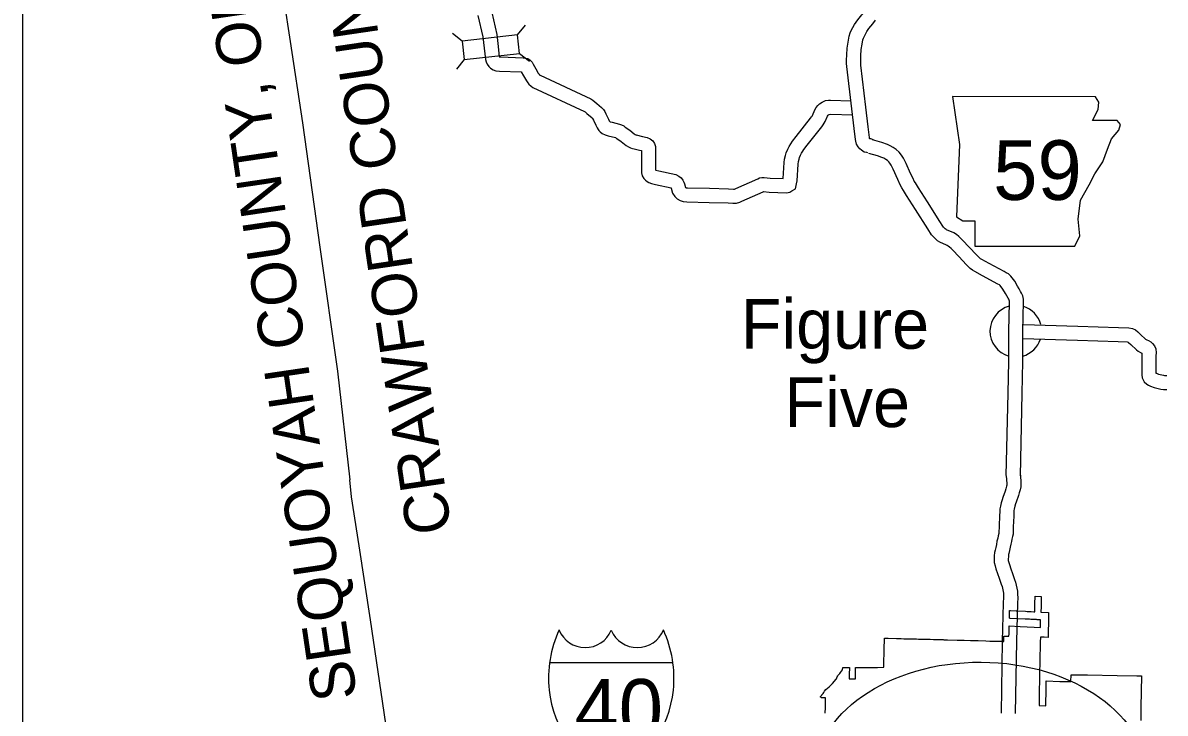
# Model space of a CAD drawing. Extents: x 535214 to 694517, y 381272 to 484355.
# Drawn here: x 535214 to 547357, y 463649 to 470990 of the extents above; entities that cross this region are included whole.
import ezdxf

# ---------------------------------------------------------------- set-up
doc = ezdxf.new("R2010")
doc.units = 0
for name, color, linetype in [('1', 7, 'Continuous'), ('21', 7, 'Continuous'), ('Level 1', 7, 'Continuous'), ('Level 10', 7, 'Continuous'), ('Level 11', 7, 'Continuous'), ('Level 20', 7, 'Continuous'), ('Level 21', 7, 'Continuous'), ('Level 23', 7, 'Continuous'), ('Level 24', 7, 'Continuous'), ('Level 6', 7, 'Continuous')]:
    doc.layers.add(name, color=color, linetype=linetype)

msp = doc.modelspace()

# ---------------------------------------------------------------- linework, layer by layer
at = {"layer": '1'}
msp.add_lwpolyline([(535214, 480223), (566227, 480223), (566227, 448175), (535214, 448175)], close=True, dxfattribs=at)
msp.add_ellipse((545395, 462932), major_axis=(1782, -9), ratio=0.706717, dxfattribs=at)
at = {"layer": 'Level 1'}
for points in [[(537589, 474021), (537668, 473434), (537852, 472112), (538054, 470793), (538187, 469927), (538371, 468606), (538557, 467284), (538691, 466131)], [(539366, 461582), (539326, 461845), (539303, 461997), (539184, 462790), (539103, 463318), (538909, 464641), (538789, 465427), (538709, 465949), (538691, 466131)]]:
    msp.add_lwpolyline(points, dxfattribs=at)
at = {"layer": 'Level 10'}
for points in [[(540052, 471068), (540103, 470840), (540118, 470722), (540131, 470601), (540138, 470575), (540149, 470549), (540169, 470524), (540187, 470507), (540214, 470490), (540243, 470481), (540282, 470477), (540513, 470470), (540535, 470428), (540567, 470373), (540581, 470353), (540594, 470337), (540616, 470318), (540637, 470302), (541184, 470047), (541190, 470043), (541197, 470038), (541211, 470024), (541265, 469978), (541269, 469974), (541270, 469971), (541279, 469955), (541304, 469902), (541318, 469874), (541329, 469857), (541338, 469845), (541351, 469829), (541373, 469812), (541405, 469798), (541437, 469788), (541513, 469769), (541517, 469768), (541522, 469765), (541529, 469760), (541575, 469727), (541628, 469685), (541653, 469670), (541674, 469661), (541692, 469654)], [(540199, 471101), (540251, 470865), (540267, 470739), (540279, 470628), (540291, 470627), (540531, 470619), (540556, 470615), (540581, 470609), (540607, 470592), (540629, 470570), (540640, 470551), (540666, 470501), (540693, 470454), (540701, 470443), (540703, 470441), (540709, 470435), (540714, 470432), (541253, 470180), (541272, 470169), (541296, 470151), (541314, 470133), (541365, 470089), (541386, 470070), (541400, 470047), (541413, 470023), (541439, 469967), (541448, 469949), (541453, 469941), (541454, 469940), (541459, 469938), (541478, 469932), (541557, 469913), (541579, 469905), (541601, 469893), (541616, 469882), (541665, 469847), (541714, 469808), (541722, 469803), (541729, 469800), (541742, 469796)], [(544196, 469606), (544185, 469611), (544159, 469615), (544130, 469636), (544110, 469651), (544093, 469673), (544075, 469701), (544068, 469730), (544065, 469749), (544052, 469866), (544027, 470075), (543974, 470524), (543971, 470558), (543971, 470592), (543972, 470648), (543978, 470721), (543986, 470785), (543997, 470847), (544009, 470883), (544021, 470908), (544056, 470973), (544089, 471023), (544134, 471075), (544160, 471108)], [(544256, 469744), (544229, 469755), (544219, 469757), (544217, 469758), (544215, 469760), (544215, 469760), (544214, 469770), (544201, 469883), (544176, 470093), (544124, 470539), (544121, 470566), (544121, 470592), (544122, 470640), (544127, 470705), (544135, 470763), (544143, 470809), (544149, 470826), (544156, 470842), (544185, 470896), (544208, 470931), (544250, 470980), (544279, 471017)], [(541735, 469798), (541802, 469782), (541849, 469772), (541883, 469758), (541910, 469734), (541929, 469705), (541938, 469674), (541940, 469650), (541941, 469425), (541944, 469424), (541975, 469416), (542156, 469378), (542189, 469360), (542213, 469341), (542231, 469318), (542242, 469297), (542249, 469277), (542260, 469240), (542260, 469240), (542264, 469237), (542264, 469236), (542281, 469235), (542514, 469230), (542716, 469224), (542767, 469222), (542778, 469222), (542780, 469222), (542792, 469228), (543027, 469332), (543046, 469340), (543070, 469345), (543094, 469344), (543157, 469339), (543296, 469333), (543307, 469503), (543312, 469540), (543320, 469578), (543330, 469609), (543345, 469647), (543361, 469675), (543377, 469704), (543396, 469733), (543434, 469782), (543588, 469976), (543599, 469991), (543604, 469997), (543607, 470005), (543634, 470063), (543648, 470089), (543666, 470111), (543682, 470128), (543711, 470148), (543746, 470163), (543777, 470166), (543799, 470167), (544017, 470161)], [(541700, 469652), (541769, 469635), (541790, 469631), (541791, 469394), (541799, 469363), (541815, 469336), (541832, 469316), (541852, 469302), (541870, 469292), (541896, 469282), (541940, 469270), (542105, 469235), (542105, 469235), (542106, 469232), (542121, 469179), (542144, 469142), (542171, 469118), (542200, 469099), (542235, 469089), (542272, 469085), (542510, 469080), (542711, 469074), (542762, 469072), (542800, 469071), (542837, 469084), (542856, 469093), (543085, 469194), (543087, 469195), (543148, 469190), (543331, 469182), (543368, 469190), (543389, 469202), (543426, 469225), (543440, 469277), (543444, 469309), (543456, 469487), (543460, 469514), (543466, 469541), (543471, 469558), (543481, 469582), (543492, 469603), (543505, 469626), (543518, 469644), (543552, 469689), (543708, 469885), (543723, 469906), (543734, 469923), (543743, 469941), (543768, 469996), (543774, 470007), (543778, 470012), (543779, 470013), (543784, 470016), (543787, 470016), (543800, 470017), (544036, 470010)], [(545818, 466174), (545836, 467048), (545845, 467388), (545845, 467710), (545853, 468023), (545850, 468053), (545843, 468085), (545831, 468114), (545821, 468132), (545805, 468161), (545789, 468188), (545758, 468241), (545718, 468295), (545693, 468319), (545669, 468333), (545647, 468345), (545486, 468430), (545410, 468474), (545396, 468482), (545384, 468491), (545368, 468506), (545354, 468520), (545272, 468607), (545207, 468676), (545187, 468697), (545165, 468716), (545139, 468739), (545112, 468755), (545087, 468767), (545057, 468778), (545034, 468789), (545028, 468792), (545018, 468801), (545001, 468818), (544993, 468827), (544961, 468879), (544831, 469086), (544736, 469234), (544702, 469288), (544690, 469307), (544677, 469333), (544652, 469388), (544603, 469494), (544590, 469522), (544575, 469551), (544555, 469584), (544529, 469615), (544499, 469643), (544467, 469665), (544435, 469683), (544405, 469697), (544346, 469719), (544246, 469747)], [(545668, 466177), (545687, 467051), (545695, 467389), (545695, 467712), (545703, 468017), (545701, 468029), (545699, 468040), (545695, 468050), (545689, 468061), (545674, 468088), (545660, 468113), (545633, 468157), (545604, 468196), (545601, 468200), (545597, 468202), (545577, 468212), (545414, 468299), (545334, 468344), (545311, 468358), (545286, 468377), (545264, 468399), (545247, 468416), (545164, 468504), (545099, 468572), (545081, 468590), (545065, 468605), (545052, 468616), (545041, 468622), (545027, 468629), (545000, 468639), (544962, 468656), (544937, 468672), (544915, 468692), (544893, 468713), (544873, 468736), (544834, 468800), (544704, 469005), (544609, 469153), (544575, 469208), (544559, 469234), (544542, 469268), (544515, 469325), (544466, 469432), (544456, 469456), (544445, 469476), (544432, 469497), (544420, 469512), (544405, 469526), (544388, 469537), (544367, 469549), (544347, 469558), (544299, 469577), (544206, 469602)], [(545668, 466171), (545673, 466092), (545673, 466073), (545671, 466061), (545663, 466036), (545655, 466011), (545631, 465942), (545623, 465919), (545614, 465885), (545606, 465850), (545601, 465821), (545600, 465786), (545597, 465755), (545592, 465634), (545591, 465570), (545588, 465559), (545583, 465534), (545577, 465509), (545569, 465478), (545563, 465443), (545557, 465412), (545550, 465382), (545543, 465359), (545541, 465323), (545539, 465286), (545541, 465250), (545550, 465214), (545558, 465185), (545575, 465135), (545592, 465085), (545614, 465020), (545623, 464997), (545628, 464977), (545638, 464926), (545639, 464906), (545640, 464883), (545636, 464820), (545626, 464416), (545613, 463648)], [(545818, 466181), (545823, 466097), (545824, 466057), (545816, 466023), (545807, 465992), (545797, 465963), (545773, 465893), (545767, 465876), (545760, 465850), (545753, 465819), (545750, 465805), (545750, 465777), (545747, 465744), (545742, 465629), (545740, 465553), (545735, 465527), (545729, 465499), (545723, 465474), (545716, 465447), (545710, 465415), (545704, 465380), (545695, 465345), (545692, 465335), (545691, 465314), (545689, 465287), (545690, 465272), (545695, 465251), (545701, 465229), (545716, 465184), (545734, 465135), (545756, 465070), (545766, 465042), (545774, 465011), (545787, 464946), (545789, 464911), (545790, 464879), (545786, 464814), (545776, 464413), (545763, 463645)]]:
    msp.add_lwpolyline(points, dxfattribs=at)
at = {"layer": 'Level 11'}
for points in [[(545850, 467783), (546429, 467765), (546863, 467750), (546973, 467747), (547012, 467738), (547041, 467725), (547067, 467704), (547096, 467677), (547150, 467625), (547154, 467622), (547162, 467618), (547180, 467610), (547204, 467597), (547224, 467580), (547244, 467555), (547258, 467522), (547261, 467480), (547260, 467447), (547260, 467266), (547265, 467263), (547286, 467255), (547306, 467250), (547339, 467242), (547351, 467240), (547376, 467241)], [(545846, 467633), (546424, 467615), (546857, 467600), (546954, 467597), (546963, 467595), (546969, 467590), (546994, 467568), (547052, 467511), (547070, 467498), (547095, 467483), (547111, 467477), (547110, 467450), (547110, 467246), (547113, 467215), (547133, 467172), (547162, 467149), (547181, 467138), (547202, 467127), (547239, 467113), (547269, 467104), (547312, 467094), (547341, 467090), (547375, 467091)]]:
    msp.add_lwpolyline(points, dxfattribs=at)
at = {"layer": 'Level 20'}
for p, q in [((540474, 470861), (540556, 470964)), ((539883, 470796), (539780, 470878)), ((539905, 470599), (539823, 470496)), ((540495, 470664), (540599, 470582))]:
    msp.add_line(p, q, dxfattribs=at)
msp.add_lwpolyline([(540474, 470861), (539883, 470796), (539905, 470599), (540495, 470664)], close=True, dxfattribs=at)
at = {"layer": 'Level 21'}
msp.add_lwpolyline([(545096, 470205), (545172, 469697), (545139, 468927), (545206, 468885), (545333, 468885), (545333, 468614), (546399, 468614), (546450, 468724), (546433, 468902), (546458, 469105), (546551, 469266), (546610, 469384), (546695, 469511), (546746, 469646), (546788, 469756), (546864, 469849), (546881, 469909), (546847, 469951), (546585, 469951), (546644, 470069), (546653, 470145), (546618, 470204)], close=True, dxfattribs=at)
at = {"layer": 'Level 23'}
msp.add_line((540814, 464188), (542124, 464188), dxfattribs=at)
for centre, radius, start, end in [((542032, 464018), 1230, 155.2204, 185.7928), ((541192, 464646), 300, 202.1459, 337.3414), ((541746, 464646), 300, 202.6586, 337.8541), ((540906, 464018), 1230, 354.2072, 24.7796), ((542009, 464028), 1209, 186.3923, 243.4571), ((540929, 464028), 1209, 296.5429, 353.6077)]:
    msp.add_arc(centre, radius, start, end, dxfattribs=at)
at = {"layer": 'Level 24'}
for start, end in [(105.0051, 253.9883), (15.05, 72.1917), (285.5017, 341.9616)]:
    msp.add_arc((545770, 467711), 275, start, end, dxfattribs=at)
at = {"layer": 'Level 6'}
for points in [[(545700, 464573), (545700, 464577), (545817, 464571), (545966, 464562), (546033, 464559), (546033, 464621), (546033, 464623), (546034, 464641), (545997, 464643), (545996, 464643), (545989, 464644), (545959, 464645), (545929, 464646), (545914, 464647), (545910, 464647), (545869, 464649), (545710, 464657), (545701, 464658), (545702, 464699), (545702, 464700), (545702, 464725), (545703, 464740), (545712, 464740), (545774, 464737), (545790, 464736), (545793, 464736), (545872, 464732), (545889, 464731), (545932, 464729), (545962, 464727), (545969, 464727), (545971, 464727), (545971, 464729), (545973, 464786), (545973, 464810), (545975, 464892), (545976, 464892), (546036, 464890), (546040, 464890), (546040, 464847), (546039, 464783), (546037, 464724), (546040, 464724), (546118, 464721), (546117, 464619), (546114, 464510), (546113, 464455), (546072, 464456), (546031, 464458), (546029, 464403), (546029, 464398), (546029, 464396), (546026, 464207), (546023, 464063), (546021, 463995), (546021, 463994), (546020, 463986), (546020, 463979), (546017, 463908), (546017, 463898), (546018, 463729), (546090, 463727), (546093, 463907), (546094, 463977), (546094, 463984), (546094, 463992), (546238, 463987), (546355, 463984), (546359, 464058), (546531, 464055), (546849, 464049), (547055, 464045), (547107, 464045), (547100, 463713), (547099, 463570)], [(543797, 463938), (543822, 463966), (543860, 464010), (543862, 464014), (543872, 464036), (543878, 464047), (543882, 464052), (543883, 464053), (543898, 464071), (543906, 464081), (543928, 464111), (543932, 464133), (543956, 464134), (543996, 464135), (544001, 464136), (544001, 464129), (544000, 464107), (543999, 464088), (543999, 464069), (543998, 464051), (543998, 464032), (543997, 464014), (544008, 464015), (544027, 464015), (544046, 464015), (544064, 464015), (544067, 464136), (544087, 464136), (544129, 464135), (544156, 464135), (544178, 464135), (544190, 464134), (544233, 464134), (544271, 464135), (544296, 464136), (544300, 464136), (544364, 464138), (544366, 464138), (544368, 464221), (544370, 464268), (544370, 464290), (544371, 464293), (544372, 464359), (544374, 464411), (544375, 464447), (544412, 464447), (544503, 464443), (544504, 464443), (544512, 464443), (544533, 464442), (544539, 464442), (544540, 464442), (544551, 464442), (544578, 464441), (544590, 464441), (544611, 464440), (544629, 464440), (544640, 464440), (544669, 464439), (544708, 464438), (544713, 464438), (544714, 464438), (544736, 464437), (544737, 464437), (544747, 464437), (544754, 464436), (544793, 464435), (544807, 464435), (544809, 464435), (544859, 464434), (544893, 464433), (544951, 464432), (544986, 464431), (544999, 464431), (545006, 464430), (545042, 464429), (545146, 464426), (545190, 464425), (545222, 464424), (545289, 464422), (545298, 464422), (545323, 464421), (545328, 464421), (545367, 464420), (545371, 464420), (545452, 464417), (545494, 464416), (545536, 464415), (545566, 464414), (545592, 464413), (545617, 464413), (545635, 464412), (545641, 464412), (545643, 464451), (545643, 464469), (545697, 464468), (545698, 464493), (545698, 464517), (545699, 464548), (545700, 464573)], [(543743, 463647), (543744, 463665), (543745, 463691), (543746, 463726), (543745, 463726), (543746, 463761), (543747, 463776), (543748, 463811), (543729, 463812), (543704, 463812), (543698, 463818), (543697, 463819), (543695, 463820), (543694, 463821), (543694, 463821), (543692, 463822), (543694, 463824), (543695, 463826), (543698, 463829), (543705, 463838), (543708, 463841), (543709, 463843), (543722, 463859), (543728, 463868), (543737, 463883), (543749, 463902), (543785, 463929), (543797, 463938)]]:
    msp.add_lwpolyline(points, dxfattribs=at)

# ---------------------------------------------------------------- texts
at = {"layer": '21'}
for s, p in [('SEQUOYAH COUNTY, OKLAHOMA', (538769, 463816)), ('CRAWFORD COUNTY', (539773, 465585))]:
    msp.add_text(s, height=475.2, rotation=98.3694, dxfattribs=at).set_placement(p)
at = {"layer": 'Level 21'}
msp.add_text('59', height=633.6, dxfattribs=at).set_placement((545529, 469107))
at = {"layer": 'Level 23'}
msp.add_text('40', height=633.6, dxfattribs=at).set_placement((541077, 463378))
at = {"layer": 'Level 24'}
for s, p in [('Figure', (542847, 467524)), ('Five', (543311, 466691))]:
    msp.add_text(s, height=528, dxfattribs=at).set_placement(p)

doc.saveas('drawing.dxf')
